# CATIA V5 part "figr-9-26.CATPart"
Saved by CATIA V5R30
Part number: Part1
Bounding box of the stored display mesh (mm): x -75 to 75, y -50 to 50, z 0 to 40
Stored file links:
  D:\PROJECTS\CATIA V56R 2020\Resources\Parts File\c09_catia_v5_6r2020_prt\figr-9-26.CATPart
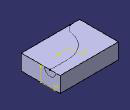
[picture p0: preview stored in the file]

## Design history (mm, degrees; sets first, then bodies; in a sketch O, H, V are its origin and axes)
Body1 (main body)
  Sketch1 on xy-plane, origin (0, 0, 0), H (1, 0, 0), V (0, 1, 0)
    line L1 (-75, 50) -> (75, 50)
    line L2 (75, 50) -> (75, -50)
    line L3 (75, -50) -> (-75, -50)
    line L4 (-75, -50) -> (-75, 50)
    axis line L5 (75, -50) -> (-75, 50)
    length L2 = 100
    length L3 = 150
    horizontal: L1 H, L3 H
    vertical: L2 V, L4 V
    midpoint: O L5
  Pad1: profile Sketch1, direction (0, 0, 1), length 40
  Sketch2 on face of Pad1, origin (75, 0, 0), H (0, 1, 0), V (0, 0, 1)
    arc A1 centre (24.1478, 40) radius 14.6047 from (9.543, 40) to (38.7525, 40) ccw
    point P1 (24.1478, 40)
    reference projected point E1 (24.1478, 40) from vertex of Sketch3
    line L1 (9.543, 40) -> (38.7525, 40)
    coincidence: P1 E1
    horizontal: L1 H
  Sketch3 on face of Pad1, origin (0, 0, 40), H (1, 0, 0), V (0, 1, 0)
    point P1 (75, 24.1478)
    line L1 (75, 24.1478) -> (28.6577, 24.1478)
    arc A1 centre (28.6577, -39.2062) radius 63.354 from (28.6577, 24.1478) to (-33.8383, -28.8149) ccw
    arc A2 centre (-62.192, -24.1005) radius 28.7429 from (-33.8383, -28.8149) to (-49.7271, -50) cw
    point P6 (-49.7271, -50)
    reference projected line E1 (75, -50) -> (75, 50) from edge [face of Pad1 | face of Pad1]
    reference projected line E2 (-75, -50) -> (75, -50) from edge [face of Pad1 | face of Pad1]
    horizontal: L1 H
    tangency: A1 L1, A2 A1
    coincidence: P1 E1, P6 E2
